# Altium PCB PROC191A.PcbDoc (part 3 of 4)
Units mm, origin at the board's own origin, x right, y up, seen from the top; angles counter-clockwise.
Board outline 150 x 100 mm, 6 copper layers (L1, L2, L3, L4, L5, L6), stack 1.608 mm thick; 309 components, 191 nets, 851 pads, 778 vias.
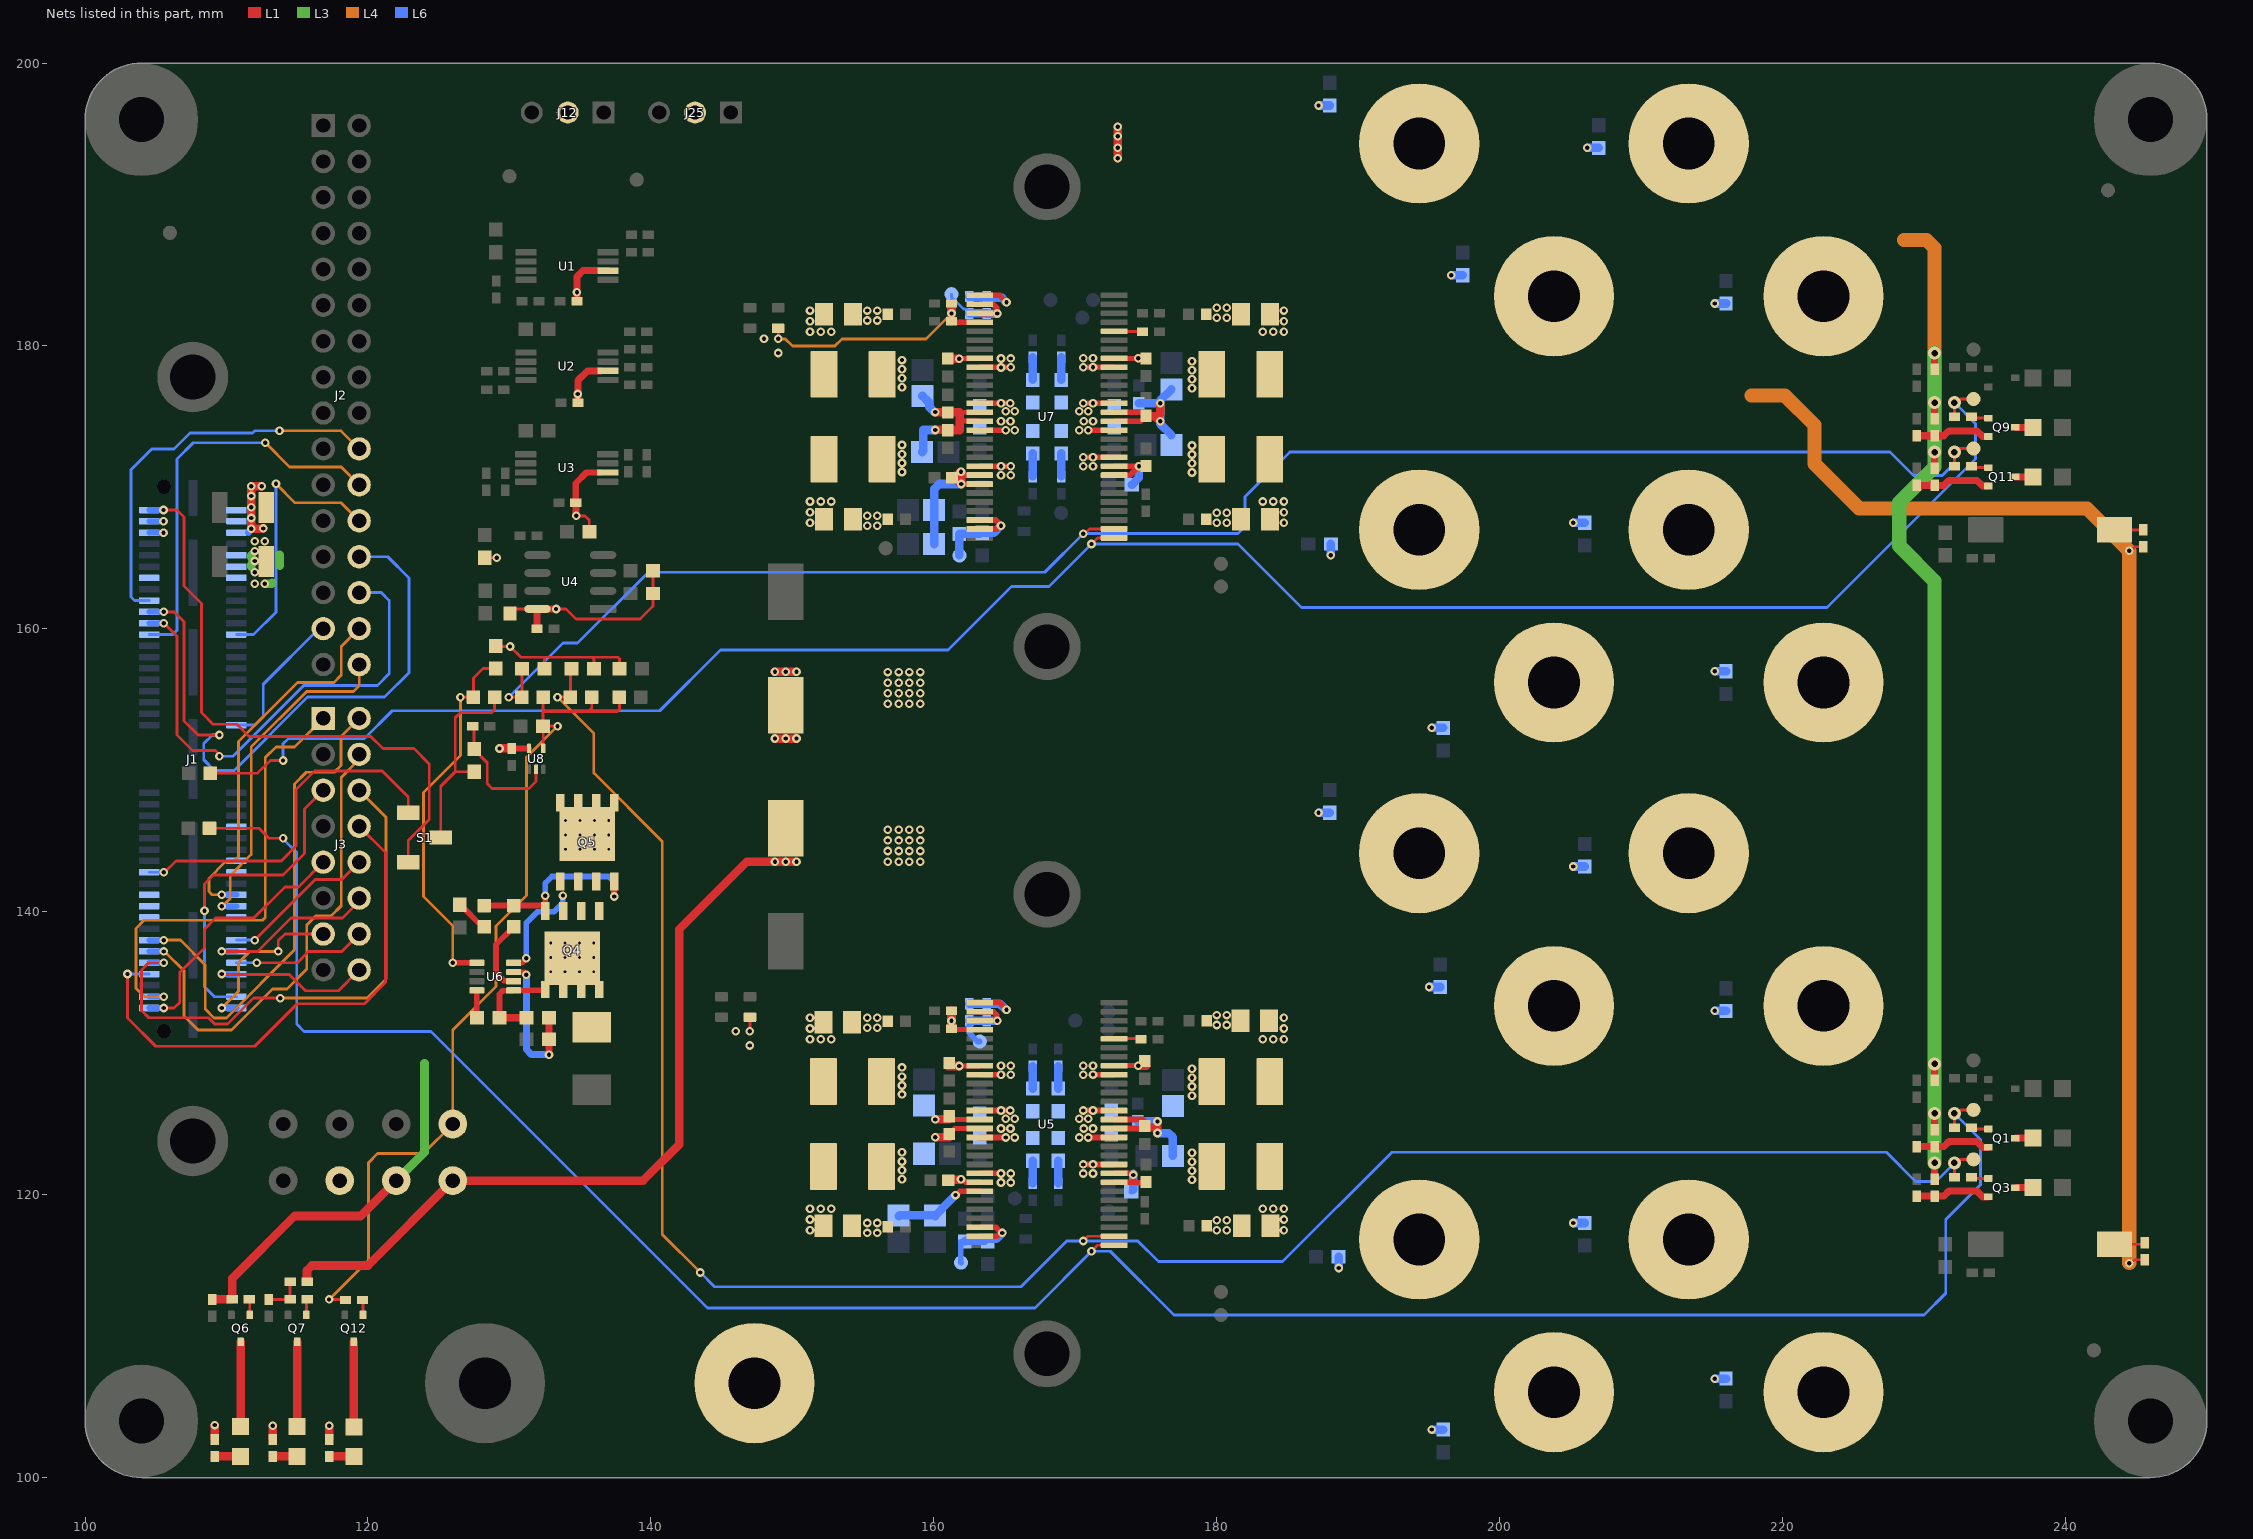
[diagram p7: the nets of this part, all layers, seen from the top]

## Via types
v1: diameter 0.61, hole 0.305, L1 to L6, tented both sides, 566 vias
v2: diameter 0.914, hole 0.457, L1 to L6, tented both sides, 188 vias
v3: diameter 0.5, hole 0.2, L1 to L6, 24 vias

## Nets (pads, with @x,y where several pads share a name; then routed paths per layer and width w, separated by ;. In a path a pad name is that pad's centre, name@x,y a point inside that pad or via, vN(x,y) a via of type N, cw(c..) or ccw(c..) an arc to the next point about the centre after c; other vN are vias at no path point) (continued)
MCASPX_SERIAL7: J1.40 J2.29 | length 10.3
  L6 w0.2: J1.40@110.705,153.2 111.998,153.2 112.6,153.802 112.6,156.08 116.54,160.02 J2.29@116.84,160.02
McASPy_ACLKR: J1.78 J3.5 | length 22.8
  L1 w0.2: v1(108.445,140.068) 108.445,141.958 109.092,142.605 113.986,142.605 115.506,144.125 115.506,147.256 J3.5@116.84,148.59
  L6 w0.2: v1(108.445,140.068) 108.445,134.7 109.145,134 J1.78@110.705,134
McASPy_ACLKX: J1.77 J3.1 | length 33.5
  L4 w0.2: v1(105.575,134) 104.2,134 103.605,134.595 103.605,138.83 104.18,139.405 112.555,139.405 112.735,139.584 112.735,150.885 113.495,151.645 114.815,151.645 J3.1@116.84,153.67
  L6 w0.4: J1.77@104.535,134 v1(105.575,134)
MCASPY_AFSR: J1.80 J3.13 | length 12
  L1 w0.2: v1(113.66,137.2) 113.66,137.96 114.13,138.43 J3.13@116.84,138.43
  L4 w0.2: v1(109.665,133.2) 110.85,134.385 110.85,136.4 111.65,137.2 v1(113.66,137.2)
  L6 w0.4: v1(109.665,133.2) J1.80@110.705,133.2
McASPy_AFSX: J1.79 J3.9 | length 18.6
  L1 w0.2: v1(105.575,133.2) 106.3,133.2 106.7,133.6 106.7,135.7 108.445,137.445 108.445,138.768 109.232,139.555 111.93,139.555 114.125,141.75 115.08,141.75 J3.9@116.84,143.51
  L6 w0.4: J1.79@104.535,133.2 v1(105.575,133.2)
McASPy_Serial0: J1.67 J3.2 | length 35.8
  L4 w0.2: v1(105.575,138) 106.75,138 108.5,136.25 108.5,133.117 109.117,132.5 110,132.5 114.815,137.315 114.815,149.038 115.637,149.86 117.615,149.86 118.1,150.345 118.1,152.39 J3.2@119.38,153.67
  L6 w0.4: J1.67@104.535,138 v1(105.575,138)
McASPy_Serial1: J1.69 J3.4 | length 34.4
  L4 w0.2: v1(105.575,137.2) 105.63,137.2 107,135.83 107,132.643 108,131.643 110.355,131.643 112.446,133.734 113.266,134.554 114.271,134.554 115.677,135.96 115.677,139.065 116.312,139.7 117.377,139.7 118.11,140.433 118.11,149.486 119.38,150.756 J3.4@119.38,151.13
  L6 w0.4: J1.69@104.535,137.2 v1(105.575,137.2)
McASPy_Serial2: J1.71 J3.6 | length 38.8
  L1 w0.2: v1(105.575,136.4) 104.51,136.4 104,135.89 104,133.022 104.51,132.512 108.738,132.512 109.17,132.08 110.08,132.08 111.9,133.9 v1(113.8,133.9)
  L4 w0.2: v1(113.8,133.9) 119.93,133.9 121.285,135.255 121.285,146.685 J3.6@119.38,148.59
  L6 w0.4: J1.71@104.535,136.4 v1(105.575,136.4)
McASPy_Serial3: J1.73 J3.8 | length 37.4
  L1 w0.2: v1(103,135.6) 103,132.5 105,130.5 112,130.5 115,133.5 119.75,133.5 121.25,135 121.25,144.18 J3.8@119.38,146.05
  L6 w0.2: v1(103,135.6) J1.73@104.535,135.6
McASPy_Serial4: J1.68 J3.10 | length 11
  L1 w0.2: v1(111.998,138) v1(111.998,138) 116.275,142.275 118.145,142.275 J3.10@119.38,143.51
  L6 w0.2: J1.68@110.705,138 v1(111.998,138)
McASPy_Serial5: J1.70 J3.12 | length 12.5
  L1 w0.2: v1(109.665,137.2) 112.2,137.2 114.555,139.555 118.205,139.555 119.38,140.73 J3.12@119.38,140.97
  L6 w0.4: v1(109.665,137.2) J1.70@110.705,137.2
McASPy_Serial6: J1.72 J3.14 | length 9.5
  L1 w0.2: v1(112.15,136.393) 115.003,136.393 115.81,137.2 118.15,137.2 J3.14@119.38,138.43
  L6 w0.2: J1.72@110.705,136.4 110.708,136.397 112.146,136.397 v1(112.15,136.393)
McASPy_Serial7: J1.74 J3.16 | length 11.9
  L1 w0.2: v1(109.665,135.6) 109.705,135.56 114.44,135.56 115.582,134.418 117.908,134.418 J3.16@119.38,135.89
  L6 w0.4: v1(109.665,135.6) J1.74@110.705,135.6
NetC15_2: C15.2 R26.1 | length 1.6
  L6 w0.6: C15.2@168.8,120.8 R26.1@168.8,122.4
NetC25_2: C25.2 R31.1 | length 1.6
  L6 w0.6: R31.1@168.8,127.5 C25.2@168.8,129.1
NetC28_1: C28.1 R96.2 U8.2 | length 9.1
  L1 w0.2: C28.1@127.4,153.134 127.5,153.034 127.5,151.475 128.438,150.537 128.438,149.062 128.775,148.725 131.392,148.725 131.886,149.219 U8.2@131.886,150.065
NetC46_2: C46.2 R34.1 | length 1.6
  L6 w0.6: C46.2@167,120.8 R34.1@167,122.4
NetC56_2: C56.2 R36.1 | length 1.6
  L6 w0.6: R36.1@167,127.5 C56.2@167,129.1
NetC64_1: C64.1 R55.1 | length 2.4
  L1 w0.4: C64.1@126.5,140.5 126.5,140.475 126.775,140.2 126.841,140.2 127.821,139.22 127.952,139.22 R55.1@128.23,138.941
NetC73_2: C73.2 R71.1 | length 1.6
  L6 w0.6: C73.2@169,170.8 R71.1@169,172.4
NetC83_2: C83.2 R76.1 | length 1.6
  L6 w0.6: R76.1@169,177.6 C83.2@169,179.2
NetC104_2: C104.2 R79.1 | length 1.6
  L6 w0.6: C104.2@167,170.8 R79.1@167,172.4
NetC114_2: C114.2 R81.1 | length 1.6
  L6 w0.6: R81.1@167,177.6 C114.2@167,179.2
NetD5_1: D5.1 R56.1 | length 1.7
  L1 w0.6: R56.1@109.167,101.4 R56.1@109.167,101.419 ; R56.1@109.35,101.519 109.635,101.519 D5.1@111,101.5
NetD5_2: D5.2 Q6.3 | length 6
  L1 w0.6: D5.2@111,103.6 Q6.3@111,109.6
NetD6_1: D6.1 R57.1 | length 1.7
  L1 w0.6: R57.1@113.278,101.5 D6.1@115,101.5
NetD6_2: D6.2 Q7.3 | length 6.3
  L1 w0.6: D6.2@115,103.35 D6.2@115,103.6 Q7.3@115,109.6
NetD11_1: D11.1 R5.1 | length 1.8
  L1 w0.6: R5.1@117.253,101.5 119,101.5 D11.1@119.01,101.49
NetD11_2: D11.2 Q12.3 | length 6
  L1 w0.6: D11.2@119,103.6 Q12.3@119,109.6
NetQ6_1: Q6.1 R61.2 | length 1.3
  L1 w0.2: Q6.1@111.65,111.5 R61.2@111.65,112.75
NetQ7_1: Q7.1 R62.2 | length 1.3
  L1 w0.2: Q7.1@115.65,111.5 R62.2@115.65,112.75
NetQ12_1: Q12.1 R27.2 | length 1.1
  L1 w0.2: R27.2@119.61,112.559 119.65,112.519 Q12.1@119.65,111.5
NetR47_1: R47.1 SW2.1 | length 2
  L1 w0.2: SW2.1@243.464,116.5 R47.1@245.5,116.5
NetR59_2: R59.2 R62.1 R65.1 | length 2.5
  L1 w0.2: R65.1@113,112.6 R62.1@114.275,112.6 ; R62.1@114.5,112.6 R59.2@114.5,113.85
NetR90_1: R90.1 SW4.1 | length 2
  L1 w0.2: SW4.1@243.464,167 R90.1@245.5,167
OUT_1M_J0: C108.2 C111.1 C113.1 J24.1 U7.37 | length 2.6
  L1 w0.4: U7.37@163.25,178.493 165.075,178.493
  L6 w0.61: v1(206.2,194) C113.1@207,194
  other v1: 164.75,178.48 165.431,178.483 164.75,179.115 165.431,179.118 155.3,181.8 156,181.8 155.3,182.5 156,182.5
OUT_1M_J1: C50.2 C53.1 C55.1 J11.1 U5.37 | length 2
  L1 w0.4: U5.37@163.25,128.493 164.415,128.493
  L6 w0.61: v1(205.2,143.2) C55.1@206,143.2
  other v1: 164.75,128.48 165.431,128.483 164.75,129.115 165.431,129.118 155.3,131.8 156,131.8 155.3,132.5 156,132.5
OUT_1P0: C80.2 L9.1 R81.2 U7.41 | length 1.8
  L1 w0.4: U7.41@163.25,175.953 165.075,175.953
  other v1: 165.075,175.378 165.725,175.378 164.75,175.953 165.4,175.953 157.75,177.091 157.75,177.722 157.75,178.353 157.75,179
OUT_1P1: C22.2 L4.1 R36.2 U5.41 | length 1.8
  L1 w0.4: U5.41@163.25,125.953 165.075,125.953
  other v1: 165.075,125.378 165.725,125.378 164.75,125.953 165.4,125.953 157.75,127.091 157.75,127.722 157.75,128.353 157.75,129
OUT_1P_J0: C108.1 C112.1 J23.1 L9.2 | length 0.8
  L6 w0.61: v1(187.2,197) C112.1@188,197
  other v1: 151.25,181 152,181 152.75,181 151.25,181.75 151.25,182.5
OUT_1P_J1: C50.1 C54.1 J10.1 L4.2 | length 0.8
  L6 w0.61: v1(187.2,147) C54.1@188,147
  other v1: 151.25,131 152,131 152.75,131 151.25,131.75 151.25,132.5
OUT_2M_J0: C91.2 C93.1 C95.1 J22.1 U7.48 | length 2.6
  L1 w0.4: U7.48@163.25,171.508 165.075,171.508
  L6 w0.61: v1(215.2,157) C95.1@216,157
  other v1: 155.3,167.3 156,167.3 155.3,168 156,168 164.75,170.863 165.431,170.865 164.75,171.498 165.431,171.5
OUT_2M_J1: C33.2 C35.1 C37.1 J9.1 U5.48 | length 2
  L1 w0.4: U5.48@163.25,121.508 164.415,121.508
  L6 w0.61: v1(215.2,107) C37.1@216,107
  other v1: 155.3,117.3 156,117.3 155.3,118 156,118 164.75,120.863 165.431,120.865 164.75,121.498 165.431,121.5
OUT_2P0: C75.2 L8.1 R79.2 U7.44 | length 1.8
  L1 w0.4: U7.44@163.25,174.048 v1(165.075,174.048)
  other v1: 157.75,171.091 157.75,171.722 157.75,172.353 157.75,173 165.725,174.048 164.75,174.679 165.425,174.679
OUT_2P1: C17.2 L3.1 R34.2 U5.44 | length 1.8
  L1 w0.4: U5.44@163.25,124.048 v1(165.075,124.048)
  other v1: 157.75,121.091 157.75,121.722 157.75,122.353 157.75,123 165.725,124.048 164.75,124.679 165.425,124.679
OUT_2P_J0: C91.1 C94.1 J21.1 L8.2 | length 0.8
  L6 w0.61: v1(195.2,153) C94.1@196,153
  other v1: 151.25,167.5 151.25,168.25 151.25,169 152,169 152.75,169
OUT_2P_J1: C33.1 C36.1 J8.1 L3.2 | length 0.8
  L6 w0.61: v1(195.2,103.4) C36.1@196,103.4
  other v1: 151.25,117.5 151.25,118.25 151.25,119 152,119 152.75,119
OUT_3M_J0: C78.2 C79.1 C82.1 J20.1 U7.20 | length 2.6
  L1 w0.4: 170.925,178.493 U7.20@172.75,178.493
  L6 w0.61: v1(215.2,183) C82.1@216,183
  other v1: 170.569,178.49 171.25,178.493 170.569,179.125 171.25,179.128 180,182 180.7,182 180,182.7 180.7,182.7
OUT_3M_J1: C20.2 C21.1 C24.1 J7.1 U5.20 | length 2
  L1 w0.4: 171.585,128.493 U5.20@172.75,128.493
  L6 w0.61: v1(215.2,133) C24.1@216,133
  other v1: 170.569,128.49 171.25,128.493 170.569,129.125 171.25,129.128 180,132 180.7,132 180,132.7 180.7,132.7
OUT_3P0: C72.2 L7.1 R76.2 U7.16 | length 1.8
  L1 w0.4: 170.925,175.953 U7.16@172.75,175.953
  other v1: 170.275,175.378 170.925,175.378 170.575,175.953 171.25,175.953 178.25,177 178.25,177.647 178.25,178.278 178.25,178.909
OUT_3P1: C14.2 L2.1 R31.2 U5.16 | length 1.8
  L1 w0.4: 170.925,125.953 U5.16@172.75,125.953
  other v1: 170.275,125.378 170.925,125.378 170.575,125.953 171.25,125.953 178.25,127 178.25,127.647 178.25,128.278 178.25,128.909
OUT_3P_J0: C78.1 C81.1 J19.1 L7.2 | length 0.8
  L6 w0.61: v1(196.582,185) C81.1@197.383,185
  other v1: 183.25,181 184,181 184.75,181 184.75,181.75 184.75,182.5
OUT_3P_J1: C20.1 C23.1 J6.1 L2.2 | length 0.8
  L6 w0.61: v1(195.01,134.686) C23.1@195.81,134.686
  other v1: 183.25,131 184,131 184.75,131 184.75,131.75 184.75,132.5
OUT_4M_J0: C66.2 C67.1 C69.1 J18.1 U7.10 | length 2.6
  L1 w0.4: 170.925,172.143 U7.10@172.75,172.143
  L6 w0.61: v1(205.2,167.5) C69.1@206,167.5
  other v1: 180,167.5 180.7,167.5 180,168.2 180.7,168.2 170.57,171.498 171.25,171.498 170.57,172.143 171.25,172.143
OUT_4M_J1: C8.2 C9.1 C11.1 J5.1 U5.10 | length 2.6
  L1 w0.4: 170.925,122.143 U5.10@172.75,122.143
  L6 w0.61: v1(205.2,118) C11.1@206,118
  other v1: 180,117.5 180.7,117.5 180,118.2 180.7,118.2 170.57,121.498 171.25,121.498 170.57,122.143 171.25,122.143
OUT_4P0: C65.2 L6.1 R71.2 U7.13 | length 1.8
  L1 w0.4: v1(170.925,174.048) U7.13@172.75,174.048
  other v1: 178.25,171.051 178.25,171.698 178.25,172.329 178.25,172.96 170.275,174.048 170.6,174.679 171.25,174.679
OUT_4P1: C7.2 L1.1 R26.2 U5.13 | length 1.8
  L1 w0.4: v1(170.925,124.048) U5.13@172.75,124.048
  other v1: 178.25,121.051 178.25,121.698 178.25,122.329 178.25,122.96 170.275,124.048 170.6,124.679 171.25,124.679
OUT_4P_J0: C66.1 C68.1 J17.1 L6.2 | length 0.8
  L6 w0.61: v1(188.068,165.2) C68.1@188.068,166
  other v1: 184.75,167.5 184.75,168.25 183.25,169 184,169 184.75,169
OUT_4P_J1: C8.1 C10.1 J4.1 L1.2 | length 0.8
  L6 w0.61: v1(188.617,114.817) C10.1@188.617,115.618
  other v1: 184.75,117.5 184.75,118.25 183.25,119 184,119 184.75,119
PD_LEDPWR0: Q11.2 R63.2 R72.1 | length 5.3
  L1 w0.5: R72.1@229.5,170.15 R63.2@230.75,170.15 231.405,170.15 ; 231.455,170.205 231.75,170.5 233.75,170.5 234.15,170.1 Q11.2@234.55,170.1
PD_LEDPWR1: Q3.2 R40.2 R45.1 | length 5.3
  L1 w0.5: R45.1@229.5,119.9 R40.2@230.75,119.9 231.405,119.9 ; 231.455,119.955 231.75,120.25 233.75,120.25 234.15,119.85 Q3.2@234.55,119.85
PD_N0: R93.2 R94.1 R95.1 TP32.1 U7.2 | length 119.8
  L1 w0.2: v1(129.963,155.177) R95.1@130.878,155.177 R94.1@130.878,157.177 ; v1(170.575,166.733) 170.686,166.733 171.016,167.063 U7.2@172.75,167.063 ; R93.2@232.15,171.5 v2(232.15,172.5) ; v2@232.343,172.5 232.593,172.75 TP32.1@233.5,172.75
  L6 w0.2: v1(129.963,155.177) 133.78,158.995 134.818,158.995 139.823,164 167.843,164 v1(170.575,166.733) 181.5,166.733 182,167.233 182,169.338 185.098,172.436 ; 185.162,172.5 227.596,172.5 229.246,170.85 231.291,170.85 232.15,171.709 v2(232.15,172.5)
PD_N1: R48.2 R54.1 R83.1 TP16.1 U5.2 | length 148.2
  L1 w0.2: v1(133.4,155.177) R83.1@134.316,155.177 134.316,157.114 R54.1@134.379,157.177 ; v1(170.575,116.733) 170.905,117.063 U5.2@172.75,117.063 ; R48.2@232.15,121.25 v2(232.15,122.25) 232.343,122.25 232.593,122.5 TP16.1@233.5,122.5
  L4 w0.2: v1(133.4,155.177) 135.968,152.61 135.968,149.81 140.806,144.972 140.806,117.194 v1(143.5,114.5)
  L6 w0.2: v1(143.5,114.5) 144.5,113.5 166.169,113.5 169.402,116.733 v1(170.575,116.733) 174.417,116.733 175.872,115.277 184.656,115.277 192.38,123 227.341,123 229.402,120.939 230.839,120.939 v2(232.15,122.25)
PD_N_L0: D10.1 Q11.3 | length 1.3
  L1 w0.5: Q11.3@236.45,170.75 D10.1@237.7,170.75
PD_N_L1: D3.1 Q3.3 | length 1.3
  L1 w0.5: Q3.3@236.45,120.5 D3.1@237.7,120.5
PD_N_R0: Q11.1 R93.1 | length 1.1
  L1 w0.2: R93.1@233.45,171.4 Q11.1@234.55,171.4
PD_N_R1: Q3.1 R48.1 | length 1.1
  L1 w0.2: R48.1@233.45,121.15 Q3.1@234.55,121.15
PLL_BYP0: C109.1 C110.1 TP28.1 U7.30 U7.31 | length 6.9
  L1 w0.4: U7.31@163.246,182.299 164.489,182.299 164.439,182.348 164.439,182.7 164.226,182.913 ; U7.30@163.25,182.938 164.201,182.938
  L6 w0.2: TP28.1@161.25,183.658 161.25,183.441 162.089,182.603 162.183,182.603 162.194,182.591 162.3,182.591 162.488,182.403 162.5,182.403 C110.1@162.5,182.303
  L6 w0.6: C110.1@162.5,182.303 C109.1@163.75,182.3 ; C109.1@163.75,182.292 v1(164.489,182.291)
PLL_BYP1: C51.1 C52.1 TP12.1 U5.30 U5.31 | length 6.8
  L1 w0.4: U5.31@163.246,132.299 v1(164.489,132.299) 164.439,132.348 164.439,132.7 164.226,132.913 ; U5.30@163.25,132.938 164.201,132.938
  L6 w0.4: C52.1@162.5,132.303 162.502,132.301 162.502,131.428 163.094,130.836 TP12.1@163.25,130.836 ; v1@164.487,132.301 v1(164.489,132.299)
  L6 w0.6: C52.1@162.502,132.301 v1@164.487,132.301
PORZ: R4.2 R27.1 R38.2 R83.2 R95.2 TP5.1 U8.4 | length 62.4
  L1 w0.2: v1(117.253,112.6) 118.369,112.6 R27.1@118.41,112.559 ; R95.2@132.38,155.177 132.38,154.156 ; U8.4@132.386,151.545 R38.2@132.386,153.127 ; v1(133.405,153.127) R38.2@132.386,153.127 ; R83.2@135.817,155.177 135.817,154.4 135.573,154.156 ; R4.2@137.776,155.177 137.776,154.284 137.648,154.156 135.573,154.156 ; 132.38,154.156 135.573,154.156 ; 132.38,154.156 132.38,153.134 R38.2@132.386,153.127
  L4 w0.2: v1(117.253,112.6) 117.26,112.6 120.03,115.37 120.03,122.256 120.678,122.905 123.905,122.905 TP5.1@126,125 126,131.664 129.053,134.717 129.053,139 131.2,141.147 131.2,150.922 v1(133.405,153.127)
PORZ_AEC: J1.1 S1.3 | length 42.2
  L1 w0.2: v1(105.55,168.4) 106.5,168.4 107,167.9 107,163.02 108.225,161.795 108.225,154.081 109.05,153.256 110.744,153.256 111.6,152.4 120.2,152.4 121.055,151.545 123.248,151.545 124.335,150.458 124.335,146.523 122.85,145.038 S1.3@122.85,143.5
  L6 w0.4: J1.1@104.535,168.4 v1(105.55,168.4)
PORZ_SELECT: R53.2 R96.1 S1.2 | length 14.1
  L1 w0.2: S1.2@125.15,145.25 125.15,148.875 126.175,149.9 ; R96.1@127.5,149.9 126.175,149.9 ; R53.2@128.955,155.177 128.955,154.286 128.753,154.084 126.538,154.084 126.175,153.722 126.175,149.9
PVDD: C26.1 C27.1 C29.1 C30.1 C32.1 C38.2 C39.2 C40.2 C41.2 C42.2 C43.2 C44.2 C45.2 C47.2 C48.1 C49.1 C59.1 C84.1 C85.1 C87.1 C88.1 C96.2 C97.2 C98.2 C99.2 C100.2 C101.2 C102.2 C103.2 C105.2 C106.1 C107.1 Q5.5 Q5.6 Q5.7 Q5.8 Q5.9 R59.1 TP6.1 U5.8 U5.9 U5.14 U5.15 U5.21 U5.36 U5.42 U5.43 U5.49 U5.50 U7.8 U7.9 U7.14 U7.15 U7.21 U7.36 U7.42 U7.43 U7.49 U7.50 | length 140.7
  L1 w0.3: C39.2@161.024,121.014 C39.2@161.067,121.057 ; v1@161.843,121.101 v1(161.927,121.101) ; v1@161.883,121.057 v1(161.927,121.101) ; v1@162.011,121.101 v1(161.927,121.101) ; U5.49@163.2,120.923 U5.49@163.25,120.873 ; U7.49@163.2,170.923 U7.49@163.25,170.873
  L1 w0.35: C40.2@161.024,125.324 161.034,125.314 U5.42@163.246,125.314 ; C97.2@161.024,175.324 U7.42@163.246,175.314 ; C38.2@161.1,124.3 161.1,124.322 161.331,124.553 161.353,124.553 161.479,124.679 U5.43@163.246,124.679 ; v1@162.004,170.234 U7.50@163.246,170.234 ; v1@162.004,170.869 U7.49@163.246,170.869 ; 162.004,174.679 U7.43@163.246,174.679 ; v1@162.045,129.103 163.225,129.103 U5.36@163.25,129.128 ; v1@162.045,179.103 163.225,179.103 U7.36@163.25,179.128 ; U5.21@172.75,129.128 v1(174.45,129.125) ; U7.21@172.75,179.128 v1(174.45,179.125)
  L1 w0.381: v1@161.983,171.101 162.212,170.873
  L1 w0.4: v1(161.534,119.977) 161.59,119.977 161.851,120.238 U5.50@163.25,120.238 ; C103.2@161.682,171.06 161.866,171.06 161.887,171.06 v1(161.927,171.101) v1@161.983,171.101 ; v1@161.927,170.241 161.939,170.241 v1@161.943,170.238 ; v1@161.927,170.241 v1@161.939,170.229 ; v1@162.091,121.051 162.269,120.873 U5.49@163.25,120.873 U5.49@163.281,120.873 ; U5.8@172.75,120.873 174.1,120.865 ; U5.9@172.75,121.508 174.1,121.5 174.1,120.865 ; U5.14@172.75,124.683 174.637,124.683 175,125.046 175,125.089 174.771,125.318 U5.15@172.75,125.318 ; U7.8@172.75,170.873 173.75,170.863 173.858,170.863 174.495,171.5 v1(174.5,171.5) ; U7.9@172.75,171.508 v1@174.21,171.508 ; U7.14@172.75,174.683 174.637,174.683 175,175.046 C102.2@175,175.067 175,175.089 174.771,175.318 U7.15@172.75,175.318 ; C45.2@174.9,120.849 174.116,120.849 174.1,120.865 ; C44.2@174.957,124.883 C44.2@175.021,124.947 ; C102.2@174.957,175.132 C102.2@175.021,175.196
  L1 w0.6: 142,138.753 146.793,143.547 v1(148.768,143.547) v1(149.53,143.547) v1(150.292,143.547) ; v1(148.768,152.247) v1(149.53,152.247) v1(150.292,152.247) ; v1(148.768,156.973) v1(149.53,156.973) v1(150.292,156.973) ; C39.2@161.067,121.057 v1@161.883,121.057 ; C44.2@175,124.818 175.049,124.769 175.812,124.769 ; C102.2@175,175.067 175.049,175.018 175.812,175.018 ; v1(175.812,124.363) 175.812,124.769 ; v1(175.812,125.176) 175.812,124.769 ; v1(175.997,174.679) 175.997,174.681 175.812,174.866 175.812,175.018 ; v1(176,175.953) 175.998,175.951 175.998,175.204 175.812,175.018
  L1 w0.61: R59.1@115.7,113.85 115.693,113.85 115.688,113.855 115.688,114.643 116.045,115 120,115 TP6.1@126,121 139.447,121 142,123.553 142,138.753 ; v1(160.1,124.062) C38.2@160.901,124.063 ; v1(160.1,125.324) C40.2@160.901,125.325 ; v1(160.1,174.062) C98.2@160.901,174.063 ; v1(160.1,175.324) C97.2@160.901,175.325 ; C41.2@161,129.1 161.1,129.1 v1(161.801,129.101) ; C96.2@161,179.1 v1(161.801,179.101) ; C38.2@161.024,124.062 C38.2@161.1,124.062 ; C40.2@161.024,125.324 C40.2@161.1,125.324 ; C98.2@161.024,174.062 161.825,174.062 161.825,175.324 C97.2@161.024,175.324 ; C103.2@161.3,170.7 C103.2@161.322,170.7 ; v1@161.927,170.241 v1@161.939,170.241 ; v1(174.45,129.125) C42.2@175,129.125 ; v1(174.45,179.125) C101.2@175,179.125 ; v1(174.5,171.5) C100.2@175,171.5 ; C103.2@161.322,170.7 161.933,170.233 161.939,170.229 v1(161.939,170.241) ; C103.2@161.322,170.7 161.866,171.06 v1(161.927,171.101) 161.932,170.709 v1(161.939,170.241)
  L6 w0.4: C47.2@173.961,120.209 C47.2@174.1,120.348 ; v1@175.715,125.2 175.8,125.115 v1@175.8,125.1
  L6 w0.6: C49.1@157.512,118.477 157.584,118.549 160.029,118.549 C48.1@160.101,118.477 ; C48.1@160.1,118.543 160.119,118.543 160.578,119.002 160.578,119.021 v1(161.534,119.977) ; C105.2@173.99,170.18 174.015,170.18 174.19,170.355 174.19,170.38 174.498,170.688 174.498,171.498 v1(174.5,171.5) ; C47.2@174.1,120.348 v1@174.1,121.5 ; C43.2@174.4,125.2 v1@175.715,125.2 ; C99.2@174.5,175.953 v1(176,175.953) ; v1(175.812,124.363) 175.814,124.361 176.601,124.361 176.9,124.062 C30.1@176.9,122.749 ; C88.1@176.8,173.7 176.799,173.7 175.999,174.499 175.999,174.677 v1(175.997,174.679) 175.996,174.681 175.996,175.072 175.998,175.075 175.998,175.951 v1(176,175.953) ; C87.1@176.8,176.932 C87.1@176.8,176.932 176.002,176.135 176.002,175.954 v1(176,175.953)
  L6 w0.61: C84.1@159.175,172.5 159.262,172.588 159.262,174.062 v1(160.1,174.062) ; C85.1@159.2,176.461 159.201,176.461 159.673,175.99 159.673,175.681 160.03,175.324 v1(160.1,175.324) ; C107.1@160.025,166 160.025,169.884 160.382,170.241 v1(161.939,170.241)
  other v1: 174.1,121.4 156.75,143.547 157.512,143.547 158.274,143.547 159.036,143.547 156.75,144.297 157.512,144.297 158.274,144.297 159.036,144.297 156.75,145.047 157.512,145.047 158.274,145.047 159.036,145.047 156.75,145.797 157.512,145.797 158.274,145.797 159.036,145.797 156.75,154.697 157.512,154.697 158.274,154.697 159.036,154.697 156.75,155.447 157.512,155.447 158.274,155.447 159.036,155.447 156.75,156.197 157.512,156.197 158.274,156.197 159.036,156.197 156.75,156.947 157.512,156.947 158.274,156.947 159.036,156.947
  other v3: 133.976,144.421 134.992,144.421 136.008,144.421 137.024,144.421 133.976,145.437 134.992,145.437 136.008,145.437 137.024,145.437 133.976,146.453 134.992,146.453 136.008,146.453 137.024,146.453
PVDD_CONN: C63.1 D4.2 J13.1 Q4.5 Q4.6 Q4.7 Q4.8 Q4.9 R50.2 U6.5 | length 7.3
  L1 w0.4: C63.1@129.3,132.512 129.3,134.184 129.534,134.418 130.275,134.418 U6.5@130.3,134.443 ; U6.5@130,134.443 U6.5@130.3,134.443 ; Q4.5@132.484,134.443 132.539,134.498 Q4.5@132.539,134.506 132.476,134.443 U6.5@130.3,134.443
  L1 w0.5: C63.1@129.3,132.512 R50.2@131.2,132.512
  other v3: 132.92,135.763 133.936,135.763 134.952,135.763 135.968,135.763 132.92,136.779 133.936,136.779 134.952,136.779 135.968,136.779 132.92,137.795 133.936,137.795 134.952,137.795 135.968,137.795
PWM1: J1.3 | length 1
  L6 w0.4: J1.3@104.535,167.6 v1(105.55,167.6)
PWM2: J1.5 | length 1
  L6 w0.4: J1.5@104.535,166.8 v1(105.55,166.8)
RESERVED1: J1.13
RESERVED3: J1.59
RESERVED4: J1.61
RESERVED5: J1.63
RESERVED6: J1.14
RESERVED7: J1.48
RESERVED8: J1.54
RESERVED9: J1.56
RESERVED10: J1.64
RESETSTATZ_AEC: J1.55 S1.1 | length 25.5
  L1 w0.2: v1(105.575,142.8) 105.63,142.8 106.43,143.6 113.874,143.6 114.925,144.651 114.925,148.64 116.232,149.947 121.014,149.947 122.85,148.111 S1.1@122.85,147
  L6 w0.2: J1.55@104.535,142.8 v1(105.575,142.8)
SDOUT_R0: R78.2 U7.24 | length 2
  L1 w0.2: U7.24@172.75,181.033 174.718,181.033 R78.2@174.75,181
SDOUT_R1: R33.2 U5.24 | length 2
  L1 w0.2: U5.24@172.75,131.033 174.718,131.033 R33.2@174.75,131
SPI_CLK: J1.17 J2.20 | length 28.2
  L4 w0.2: v1(113.75,174) 118.1,174 J2.20@119.38,172.72
  L6 w0.2: J1.17@104.535,162 103.5,162 103.25,162.25 103.25,171.25 104.72,172.72 106.286,172.72 107.41,173.845 111.845,173.845 112,174 v1(113.75,174)
SPI_CS0: J1.23 J2.22 | length 28.8
  L4 w0.2: v1(112.75,173.16) 114.46,171.45 118.11,171.45 J2.22@119.38,170.18
  L6 w0.2: J1.23@104.535,159.6 106.2,159.6 106.5,159.9 106.5,172.006 107.654,173.16 v1(112.75,173.16)
SPI_CS1: J1.24 J2.24 | length 19.5
  L4 w0.2: v1(113.5,170.256) 114.846,168.91 118.11,168.91 J2.24@119.38,167.64
  L6 w0.2: J1.24@110.705,159.6 111.921,159.6 113.5,161.179 v1(113.5,170.256)
SPI_D0: J1.19 J2.26 | length 43.7
  L1 w0.2: v1(105.575,161.2) 106.304,161.2 107,160.504 107,153.5 108,152.5 v1(109.5,152.5)
  L6 w0.2: v1(109.5,152.5) 109,152.5 108.395,151.895 108.395,150.749 109.145,150 110.55,150 115.727,155.177 121.177,155.177 122.9,156.9 122.9,163.6 121.4,165.1 J2.26@119.38,165.1
  L6 w0.4: J1.19@104.535,161.2 v1(105.575,161.2)
SPI_D1: J1.21 J2.28 | length 35
  L1 w0.2: v1(105.575,160.4) 106.5,159.475 106.5,152.5 107.595,151.405 109.215,151.405 109.332,151.288 109.332,151.279 109.5,151.111 v1(109.5,151)
  L6 w0.2: v1(109.5,151) 110.459,151 115.459,156 120.675,156 121.5,156.825 121.5,162 120.94,162.56 J2.28@119.38,162.56
  L6 w0.4: J1.21@104.535,160.4 v1(105.575,160.4)
STBY_LEDPWR0: Q9.2 R58.2 R60.1 | length 5.3
  L1 w0.5: R60.1@229.5,173.65 R58.2@230.75,173.65 231.405,173.65 ; 231.455,173.705 231.75,174 233.75,174 234.15,173.6 Q9.2@234.55,173.6
STBY_LEDPWR1: Q1.2 R37.2 R39.1 | length 5.3
  L1 w0.5: R39.1@229.5,123.4 R37.2@230.75,123.4 231.405,123.4 ; 231.455,123.455 231.75,123.75 233.75,123.75 234.15,123.35 Q1.2@234.55,123.35
STBY_N0: R86.1 R88.2 TP29.1 U7.1 | length 147.1
  L1 w0.2: R86.1@108.851,149.8 112.205,149.8 113.105,150.7 113.998,150.7 v1(114,150.698) ; v1(171.15,166) 171.577,166.428 U7.1@172.75,166.428 ; R88.2@232.15,175 v2(232.15,176) ; v2@232.343,176 232.593,176.25 TP29.1@233.5,176.25
  L6 w0.2: v1(114,150.698) 114,151.883 114.372,152.255 119.76,152.255 121.721,154.216 140.629,154.216 144.912,158.5 161,158.5 165.5,163 168.15,163 v1(171.15,166) 181.5,166 186,161.5 223.142,161.5 233.648,172.005 233.648,174.502 v2(232.15,176)
STBY_N1: R41.1 R43.2 TP13.1 U5.1 | length 166.6
  L1 w0.2: R41.1@108.8,145.9 108.805,145.905 112.295,145.905 113,145.2 v1(114,145.2) ; v1(171.15,116) 171.577,116.428 U5.1@172.75,116.428 ; R43.2@232.15,124.75 v2(232.15,125.75) ; v2@232.343,125.75 232.593,126 TP13.1@233.5,126
  L6 w0.2: v1(114,145.2) 114,145.154 114.969,144.186 114.969,132.071 115.489,131.55 124.45,131.55 144,112 167.15,112 v1(171.15,116) 172.477,116 176.977,111.5 230,111.5 231.537,113.037 231.537,118.245 234,120.707 234,123.9 v2(232.15,125.75)
STBY_N_L0: D8.1 Q9.3 | length 1.3
  L1 w0.5: Q9.3@236.45,174.25 D8.1@237.7,174.25
STBY_N_L1: D1.1 Q1.3 | length 1.3
  L1 w0.5: Q1.3@236.45,124 D1.1@237.7,124
STBY_N_R0: Q9.1 R88.1 | length 1.1
  L1 w0.2: R88.1@233.45,174.9 Q9.1@234.55,174.9
STBY_N_R1: Q1.1 R43.1 | length 1.1
  L1 w0.2: R43.1@233.45,124.65 Q1.1@234.55,124.65
UART_RX: J1.62 J2.32 | length 24.1
  L4 w0.2: v1(109.665,140.4) 109.72,140.4 110.27,140.949 110.27,142.57 111.745,144.045 111.745,151.645 115.675,155.575 118.975,155.575 119.38,155.98 J2.32@119.38,157.48
  L6 w0.4: v1(109.665,140.4) J1.62@110.705,140.4
UART_TX: J1.60 J2.30 | length 26.9
  L4 w0.2: v1@109.72,141.2 v1(109.665,141.2) 108.994,141.2 108.754,141.44 108.754,142.365 109.9,143.51 110.45,143.51 110.85,143.91 110.85,152.04 115.02,156.21 117.59,156.21 118.11,156.73 118.11,158.75 J2.30@119.38,160.02
  L6 w0.4: v1(109.665,141.2) J1.60@110.705,141.2
VDDIO: C2.2 C3.2 C4.2 C5.2 C6.2 C12.1 C13.1 C57.2 C70.1 C71.1 J1.10 J1.12 R2.1 R7.2 R8.2 R17.1 R18.1 R20.1 R28.2 R47.2 R52.2 R54.2 R61.1 R64.1 R73.2 R90.2 R94.2 TP33.1 U1.6 U2.6 U3.6 U4.8 U5.32 U7.32 U8.5 | length 179.5
  L1 w0.2: R8.2@128.27,165.024 v1(129.099,165.024) ; R52.2@129.032,158.788 129.07,158.75 v1(130.048,158.75) 130.798,158 132.435,158 ; R17.1@130.346,161.409 U4.8@131.911,161.409 ; R94.2@132.478,157.177 132.478,157.957 132.435,158 ; v1(133.3,161.409) 134,161.409 134.71,160.698 139.244,160.698 140.15,161.605 R18.1@140.15,162.5 R20.1@140.15,164.1 ; v1@134.745,167.979 135.347,167.979 135.64,167.686 R7.2@135.64,166.912 ; R54.2@135.979,157.177 135.979,157.838 135.817,158 ; R2.1@137.688,157.089 R2.1@137.776,157.177 137.776,157.883 137.659,158 135.817,158 ; v1(147,131.55) R28.2@147,132.55 ; v1(149,180.5) R73.2@149,181.25 ; v1(244.5,115.167) 244.928,115.406 R47.2@245.606,115.406 ; v1(244.5,165.514) 244.611,165.514 244.897,165.8 R90.2@245.5,165.8 ; 132.435,158 135.817,158
  L1 w0.35: R17.1@130.041,161.079 130.041,161.104 R17.1@130.346,161.409 ; U4.8@131.95,161.37 U4.8@131.949,161.371 ; U1.6@136.962,185.333 U1.6@136.972,185.322 ; C13.1@161.25,131.75 C13.1@161.308,131.693 ; C13.1@161.332,131.668 U5.32@163.25,131.668 ; U5.32@163.225,131.693 U5.32@163.25,131.668 ; U7.32@163.25,181.668 U7.32@163.257,181.675 ; U5.32@163.257,131.675 U5.32@163.25,131.668 ; U4.8@131.949,161.371 131.911,161.409 U4.8@131.986,161.409 U4.8@131.949,161.371
  L1 w0.4: C57.2@130.15,151.545 U8.5@131.386,151.545 ; C71.1@161.425,181.668 U7.32@163.25,181.668
  L1 w0.45: C5.2@134.7,168.9 134.7,170.3 135.45,171.05 U3.6@136.45,171.05
  L1 w0.5: C6.2@131.95,160 U4.8@131.95,161.37 ; U4.8@131.986,161.409 v1(133.3,161.409) ; C5.2@134.7,168.9 134.712,168.888 134.712,168.012 v1(134.724,168) v1@134.745,167.979 ; C3.2@134.773,183.148 v1(134.773,183.8) 134.773,184.895 135.2,185.322 U1.6@136.972,185.322 ; C4.2@134.85,176 134.844,176.006 134.844,176.595 v1(134.837,176.601) 134.858,176.622 134.858,177.57 135.524,178.236 U2.6@136.467,178.236 ; R7.2@135.64,166.912 R7.2@135.674,166.878
  L1 w0.6: R64.1@109,112.6 R61.1@110.4,112.6 ; v1(129.3,151.545) C57.2@130.15,151.545
  L1 w0.61: R61.1@110.4,112.6 110.4,114.084 114.816,118.5 119.5,118.5 TP33.1@122,121 TP33.1@122.118,121.118 ; v1@161.24,182.31 161.24,182.3 C71.1@161.25,181.75 ; C13.1@161.25,131.75 v1(161.25,132.3) C12.1@161.25,133 ; v1(161.25,182.3) C70.1@161.25,183
  L3 w0.6: 111.745,164.4 111.745,164.542 112,164.797 v1(112,164.8) 112,164.803 111.745,165.058 111.745,165.2 ; v1(112.7,163.2) 112.702,163.202 113.202,163.202 113.25,163.25 ; 113.75,164.45 113.75,165.25
  L3 w0.61: TP33.1@122,121 124,123 ; 124,123.168 124,123 ; 124,129.28 124,123
  L4 w0.2: v1(149,180.5) 149.5,180.5 150,180 153,180 153.5,180.5 159.45,180.5 v1(161.25,182.3)
  L4 w1: 217.81,176.5 220.155,176.5 222.25,174.405 222.25,171.668 225.418,168.5 241.514,168.5 v1(244.5,165.514) v1(244.5,115.167)
  other v1: 147,130.55 146,131.55 112,163.2 112,164 112,165.5 112,166.2 112.7,166.2 149,179.5 148,180.5
VIN1_EN: R52.1 R53.1 U6.1 | length 26.5
  L1 w0.2: v1(126.538,155.177) R53.1@127.453,155.177 127.453,156.522 128.132,157.2 129.02,157.2 R52.1@129.032,157.188
  L1 w0.4: v1(126,136.394) U6.1@127.7,136.393
  L4 w0.2: v1(126,136.394) 126,139 123.925,141.075 123.925,148.425 126.538,151.038 v1(126.538,155.177)
VIN1_GATE: Q4.4 Q5.4 R49.1 R55.2 | length 13.6
  L1 w0.4: R55.2@128.23,140.443 R49.1@130.316,140.443 132.434,140.443 Q4.4@132.539,140.338 ; v1(132.525,141.135) 132.539,141.121 Q4.4@132.539,140.338 ; Q4.4@132.539,140.068 Q4.4@132.539,140.338 ; v1@137.405,141.094 Q5.4@137.405,142.147
  L6 w0.4: v1(132.525,141.135) 132.54,141.149 132.54,142.04 133,142.5 137,142.5 137.418,142.082 v1(137.418,141.081)
VIN1_GATE_R: R49.2 U6.6 | length 5.3
  L1 w0.4: U6.6@130.3,135.093 130.275,135.118 129.638,135.118 129.053,135.703 129.053,137.682 130.313,138.941 R49.2@130.316,138.941
VIN1_OV: R50.1 R51.2 U6.7 | length 10.6
  L1 w0.4: U6.7@130.325,135.718 131.042,135.718 v1(131.2,135.56)
  L1 w0.5: v1(132.8,129.9) 132.802,129.902 132.802,130.986 R51.2@132.804,130.988 ; R50.1@132.8,132.512 132.802,132.51 R51.2@132.802,131.024
  L6 w0.5: v1(131.2,135.56) 131.2,130.263 131.563,129.9 v1(132.8,129.9)
VIN1_SRC: Q4.1 Q4.2 Q4.3 Q5.1 Q5.2 Q5.3 U6.8 | length 7.2
  L1 w0.4: U6.8@130.3,136.393 130.878,136.393 v1(131.2,136.715)
  L6 w0.4: v1(131.2,136.715) 131.2,139.224 131.976,140 133.14,140 133.782,140.642 v1(133.782,141.148)
VIN1_VCAP: C63.2 U6.4 | length 1.9
  L1 w0.4: C63.2@127.7,132.512 U6.4@127.7,134.443
VR_RET0: C109.2 C110.2 U7.29 | length 5
  L1 w0.4: U7.29@163.25,183.573 164.653,183.573 v1@165.139,183.086
  L6 w0.6: C110.2@162.5,183.491 C109.2@163.75,183.491 C109.2@163.75,183.399 ; C109.2@163.75,183.391 164.824,183.391 165.136,183.078 v1(165.139,183.078)
VR_RET1: C51.2 C52.2 U5.29 | length 4.9
  L1 w0.4: U5.29@163.25,133.573 164.653,133.573 v1(165.139,133.086)
  L6 w0.6: C52.2@162.5,133.503 C51.2@163.734,133.503 164.666,133.503 165.082,133.086 v1(165.139,133.086)
VREG0: C74.2 C76.1 TP23.1 U7.54 U7.55 | length 8
  L1 w0.4: U7.55@163.25,167.063 164.454,167.063 164.692,167.3 v1(164.748,167.3) 164.748,167.329 164.38,167.698 U7.54@163.25,167.698
  L6 w0.6: TP23.1@161.81,165.192 161.806,165.197 161.806,166.696 C76.1@161.801,166.7 161.817,166.716 163.234,166.716 C74.2@163.25,166.733 ; C74.2@163.25,166.758 163.285,166.792 164.238,166.792 164.746,167.3 v1(164.748,167.3)
VREG1: C16.2 C18.1 TP7.1 U5.54 U5.55 | length 7.8
  L1 w0.4: U5.55@163.25,117.063 164.454,117.063 164.692,117.3 v1@164.748,117.3 ; U5.54@163.25,117.698 164.39,117.698 164.395,117.693 164.399,117.693 164.792,117.3 v1(164.848,117.3) v1@164.848,117.323
  L6 w0.4: C18.1@161.902,116.674 161.902,115.226 TP7.1@161.929,115.2
  L6 w0.6: C18.1@162.2,116.7 162.26,116.76 163.618,116.76 163.734,116.877 164.425,116.877 v1(164.848,117.3)
VSYS5V0: C1.2 J1.2 J1.4 J1.6 J12.2 J25.2 R5.2 R37.1 R40.1 R42.1 R56.2 R57.2 R58.1 R63.1 R66.1 TP4.1 | length 93
  L1 w0.5: R40.1@230.75,121.1 v2(230.75,122.25) ; R37.1@230.75,124.6 v2(230.75,125.75) ; R42.1@230.75,128.1 v2(230.75,129.25) ; R63.1@230.75,171.35 v2(230.75,172.5) ; R58.1@230.75,174.85 v2(230.75,176) ; R66.1@230.75,178.35 v2(230.75,179.5)
  L1 w0.6: R56.2@109.167,102.7 v1(109.167,103.716) ; R57.2@113.278,102.7 v1(113.278,103.671) ; R5.2@117.253,102.7 117.253,103.672 117.257,103.675 v1(117.257,103.678)
  L1 w0.61: v1(112.5,170.072) v1(111.745,170.072) v1(111.745,169.392) v1(111.745,168.592) v1(111.745,167.837) v1(111.745,167.072) 112.572,167.072 v1(112.6,167.1) ; v1(173,193.265) v1(173,194.02) v1(173,194.82) v1(173,195.5)
  L3 w1: v2(230.75,122.25) v2(230.75,125.75) v2(230.75,129.25) 230.75,163.372 228.25,165.872 228.25,168.945 230.75,171.445 v2(230.75,172.5) v2(230.75,176) v2(230.75,179.5)
  L4 w1: 228.58,187.5 230.164,187.5 230.75,186.914 v2(230.75,179.5) v2(230.75,176) v2(230.75,172.5)
  L6 w0.5: 111.553,166.82 v1@111.639,166.906
pads on no net: FID1.1 FID2.1 FID3.1 FID4.1 FID5.1 FID6.1 J1. U1.5 U1.7 U3.5 U3.7 U4.1 U5.22 U5.51 U6.3 U7.22 U7.51 U8.1

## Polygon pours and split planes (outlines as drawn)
PVDD on L1 "L1_PVDD_P182" (solid, remove dead copper, pour order 182): 132.973,148.561 133.012,148.6 138,148.6 138,143.6 132.9,143.6 132.9,148.6
PVDD on L1 "L1_PVDD_P015" (solid, remove dead copper, pour order 15): 161.1,123.761 162.145,123.761 162.145,125.9 161.1,125.9
PVDD on L1 "L1_PVDD_P180" (solid, remove dead copper, pour order 180): 162.054,170.876 162.054,170.238 164.193,170.238 164.193,170.876
VSYS5V0 on L1 "L1_VSYS5V0_P020" (solid, remove dead copper, pour order 20): 111.164,167 114.164,167 ccw(c114.164,167.4) 114.564,167.4 116.364,167.4 116.364,176 116.364,182 121.364,187 172.752,187 173.748,187.666 173.748,195.616 172.864,196.5 111.864,196.5 110.864,195.5 110.864,167.3 ccw(c111.164,167.3)
GND on L1 "L1_GND_P149" (solid, remove dead copper, pour order 179): 104,200 246,200 cw(c246,196) 250,196 250,104 cw(c246,104) 246,100 104,100 cw(c104,104) 100,104 100,196 cw(c104,196)
VDDIO on L1 "L1_VDDIO_P016" (solid, remove dead copper, pour order 16): 111.4,162.8 113,162.8 113,166.5 111.4,166.5
PVDD on L1 "L1_PVDD_P178" (solid, remove dead copper, pour order 178): 162.054,175.321 162.054,174.683 164.193,174.683 164.193,175.321
PLL_BYP0 on L1 "L1_PLL_BYP0_P176" (solid, remove dead copper, pour order 176): 162.304,182.941 162.304,182.303 164.443,182.303 164.443,182.941
PVDD on L1 "L1_PVDD_P166" (solid, remove dead copper, pour order 166): 171.804,175.321 171.804,174.683 174.818,174.683 174.818,175.321
PVDD on L1 "L1_PVDD_P165" (solid, remove dead copper, pour order 165): 171.804,171.511 171.804,170.873 174.1,170.873 174.1,171.511
VREG0 on L1 "L1_VREG0_P164" (solid, remove dead copper, pour order 164): 162.304,167.701 162.304,167.063 164.564,167.063 164.564,167.701
VREG1 on L1 "L1_VREG1_P163" (solid, remove dead copper, pour order 163): 162.304,117.701 162.304,117.063 164.595,117.063 164.595,117.701
PVDD on L1 "L1_PVDD_P162" (solid, remove dead copper, pour order 162): 171.804,125.321 171.804,124.683 174.818,124.683 174.818,125.321
PVDD on L1 "L1_PVDD_P161" (solid, remove dead copper, pour order 161): 171.804,121.511 171.804,120.873 173.943,120.873 173.943,121.511
PVDD on L1 "L1_PVDD_P160" (solid, remove dead copper, pour order 160): 162.054,125.318 162.054,124.679 164.193,124.679 164.193,125.318
PLL_BYP1 on L1 "L1_PLL_BYP1_P029" (solid, remove dead copper, pour order 29): 162.3,132.938 162.3,132.299 164.439,132.299 164.439,132.938
PVDD_CONN on L1 "L1_PVDD_CONN_P159" (solid, remove dead copper, pour order 159): 132,139 137,139 138,138 138,130.5 132,130.5
PVDD on L1 "L1_PVDD_P091" (solid, remove dead copper, pour order 91): 159.6,157.36 159.6,143.16 156.25,143.16 156.25,157.36
OUT_4P_J1 on L1 "L1_OUT_4P_J1_P158" (solid, remove dead copper, pour order 158): 182.75,124 182.75,116.75 185.25,116.75 185.25,124
OUT_2P_J1 on L1 "L1_OUT_2P_J1_P155" (solid, remove dead copper, pour order 155): 153.25,116.75 153.25,124 150.75,124 150.75,116.75
OUT_3P_J1 on L1 "L1_OUT_3P_J1_P151" (solid, remove dead copper, pour order 151): 182.75,133.25 182.75,126 185.25,126 185.25,133.25
OUT_1P_J1 on L1 "L1_OUT_1P_J1_P142" (solid, remove dead copper, pour order 142): 153.25,126 153.25,133.25 150.75,133.25 150.75,126
OUT_4P1 on L1 "L1_OUT_4P1_P140" (solid, remove dead copper, pour order 140): 177.75,120.25 179.75,120.25 179.75,123.75 177.75,123.75
OUT_3P1 on L1 "L1_OUT_3P1_P134" (solid, remove dead copper, pour order 134): 177.75,126.25 179.75,126.25 179.75,129.75 177.75,129.75
OUT_1P1 on L1 "L1_OUT_1P1_P133" (solid, remove dead copper, pour order 133): 158.25,129.75 156.25,129.75 156.25,126.25 158.25,126.25
OUT_2P1 on L1 "L1_OUT_2P1_P132" (solid, remove dead copper, pour order 132): 158.25,123.75 156.25,123.75 156.25,120.25 158.25,120.25
OUT_4M_J1 on L1 "L1_OUT_4M_J1_P131" (solid, remove dead copper, pour order 131): 182.5,116.75 182.5,118.75 179,118.75 179,116.75
OUT_2M_J1 on L1 "L1_OUT_2M_J1_P106" (solid, remove dead copper, pour order 106): 153.5,118.75 153.5,116.75 157,116.75 157,118.75
OUT_3M_J1 on L1 "L1_OUT_3M_J1_P105" (solid, remove dead copper, pour order 105): 182.5,131.25 182.5,133.25 179,133.25 179,131.25
OUT_1M_J1 on L1 "L1_OUT_1M_J1_P104" (solid, remove dead copper, pour order 104): 153.5,133.25 153.5,131.25 157,131.25 157,133.25
OUT_3P1 on L1 "L1_OUT_3P1_P103" (solid, remove dead copper, pour order 103): 171.4,124.993 170.164,124.993 cw(c170.164,125.256) 169.9,125.256 169.9,126.156 cw(c170.136,126.156) 170.136,126.393 171.4,126.393 cw(c171.4,126.193) 171.6,126.193 171.6,125.193 cw(c171.4,125.193)
OUT_4P1 on L1 "L1_OUT_4P1_P101" (solid, remove dead copper, pour order 101): 171.4,123.653 170.164,123.653 cw(c170.164,123.917) 169.9,123.917 169.9,124.817 cw(c170.136,124.817) 170.136,125.053 171.4,125.053 cw(c171.4,124.853) 171.6,124.853 171.6,123.853 cw(c171.4,123.853)
OUT_1P1 on L1 "L1_OUT_1P1_P099" (solid, remove dead copper, pour order 99): 164.6,126.337 165.836,126.337 cw(c165.836,126.074) 166.1,126.074 166.1,125.174 cw(c165.864,125.174) 165.864,124.937 164.6,124.937 cw(c164.6,125.137) 164.4,125.137 164.4,126.137 cw(c164.6,126.137)
OUT_2P1 on L1 "L1_OUT_2P1_P097" (solid, remove dead copper, pour order 97): 164.6,125.064 165.836,125.064 cw(c165.836,124.8) 166.1,124.8 166.1,123.9 cw(c165.864,123.9) 165.864,123.664 164.6,123.664 cw(c164.6,123.864) 164.4,123.864 164.4,124.864 cw(c164.6,124.864)
OUT_2M_J1 on L1 "L1_OUT_2M_J1_P095" (solid, remove dead copper, pour order 95): 164.6,121.882 165.6,121.882 cw(c165.6,121.682) 165.8,121.682 165.8,120.682 cw(c165.6,120.682) 165.6,120.482 164.6,120.482 cw(c164.6,120.682) 164.4,120.682 164.4,121.682 cw(c164.6,121.682)
OUT_4M_J1 on L1 "L1_OUT_4M_J1_P094" (solid, remove dead copper, pour order 94): 170.42,122.527 171.42,122.527 cw(c171.42,122.327) 171.62,122.327 171.62,121.327 cw(c171.42,121.327) 171.42,121.127 170.42,121.127 cw(c170.42,121.327) 170.22,121.327 170.22,122.327 cw(c170.42,122.327)
OUT_3M_J1 on L1 "L1_OUT_3M_J1_P093" (solid, remove dead copper, pour order 93): 170.419,129.509 171.419,129.509 cw(c171.419,129.309) 171.619,129.309 171.619,128.309 cw(c171.419,128.309) 171.419,128.109 170.419,128.109 cw(c170.419,128.309) 170.219,128.309 170.219,129.309 cw(c170.419,129.309)
OUT_1M_J1 on L1 "L1_OUT_1M_J1_P092" (solid, remove dead copper, pour order 92): 164.6,129.5 165.6,129.5 cw(c165.6,129.3) 165.8,129.3 165.8,128.3 cw(c165.6,128.3) 165.6,128.1 164.6,128.1 cw(c164.6,128.3) 164.4,128.3 164.4,129.3 cw(c164.6,129.3)
OUT_4P0 on L1 "L1_OUT_4P0_P090" (solid, remove dead copper, pour order 90): 177.75,170.25 179.75,170.25 179.75,173.75 177.75,173.75
OUT_3P0 on L1 "L1_OUT_3P0_P089" (solid, remove dead copper, pour order 89): 177.75,176.25 179.75,176.25 179.75,179.75 177.75,179.75
OUT_1P0 on L1 "L1_OUT_1P0_P088" (solid, remove dead copper, pour order 88): 158.25,179.75 156.25,179.75 156.25,176.25 158.25,176.25
OUT_2P0 on L1 "L1_OUT_2P0_P087" (solid, remove dead copper, pour order 87): 158.25,173.75 156.25,173.75 156.25,170.25 158.25,170.25
OUT_4P_J0 on L1 "L1_OUT_4P_J0_P086" (solid, remove dead copper, pour order 86): 182.75,174 182.75,166.75 185.25,166.75 185.25,174
OUT_4M_J0 on L1 "L1_OUT_4M_J0_P064" (solid, remove dead copper, pour order 64): 182.5,166.75 182.5,168.75 179,168.75 179,166.75
OUT_2P_J0 on L1 "L1_OUT_2P_J0_P063" (solid, remove dead copper, pour order 63): 153.25,166.75 153.25,174 150.75,174 150.75,166.75
OUT_2M_J0 on L1 "L1_OUT_2M_J0_P062" (solid, remove dead copper, pour order 62): 153.5,168.75 153.5,166.75 157,166.75 157,168.75
OUT_3P_J0 on L1 "L1_OUT_3P_J0_P061" (solid, remove dead copper, pour order 61): 182.75,183.25 182.75,176 185.25,176 185.25,183.25
OUT_3M_J0 on L1 "L1_OUT_3M_J0_P060" (solid, remove dead copper, pour order 60): 182.5,181.25 182.5,183.25 179,183.25 179,181.25
OUT_1P_J0 on L1 "L1_OUT_1P_J0_P059" (solid, remove dead copper, pour order 59): 153.25,176 153.25,183.25 150.75,183.25 150.75,176
OUT_1M_J0 on L1 "L1_OUT_1M_J0_P058" (solid, remove dead copper, pour order 58): 153.5,183.25 153.5,181.25 157,181.25 157,183.25
OUT_3P0 on L1 "L1_OUT_3P0_P057" (solid, remove dead copper, pour order 57): 171.4,174.993 170.164,174.993 cw(c170.164,175.256) 169.9,175.256 169.9,176.156 cw(c170.136,176.156) 170.136,176.393 171.4,176.393 cw(c171.4,176.193) 171.6,176.193 171.6,175.193 cw(c171.4,175.193)
OUT_4P0 on L1 "L1_OUT_4P0_P055" (solid, remove dead copper, pour order 55): 171.4,173.653 170.164,173.653 cw(c170.164,173.917) 169.9,173.917 169.9,174.817 cw(c170.136,174.817) 170.136,175.053 171.4,175.053 cw(c171.4,174.853) 171.6,174.853 171.6,173.853 cw(c171.4,173.853)
OUT_1P0 on L1 "L1_OUT_1P0_P054" (solid, remove dead copper, pour order 54): 164.6,176.337 165.836,176.337 cw(c165.836,176.074) 166.1,176.074 166.1,175.174 cw(c165.864,175.174) 165.864,174.937 164.6,174.937 cw(c164.6,175.137) 164.4,175.137 164.4,176.137 cw(c164.6,176.137)
OUT_2P0 on L1 "L1_OUT_2P0_P053" (solid, remove dead copper, pour order 53): 164.6,175.064 165.836,175.064 cw(c165.836,174.8) 166.1,174.8 166.1,173.9 cw(c165.864,173.9) 165.864,173.664 164.6,173.664 cw(c164.6,173.864) 164.4,173.864 164.4,174.864 cw(c164.6,174.864)
OUT_2M_J0 on L1 "L1_OUT_2M_J0_P052" (solid, remove dead copper, pour order 52): 164.6,171.882 165.6,171.882 cw(c165.6,171.682) 165.8,171.682 165.8,170.682 cw(c165.6,170.682) 165.6,170.482 164.6,170.482 cw(c164.6,170.682) 164.4,170.682 164.4,171.682 cw(c164.6,171.682)
OUT_4M_J0 on L1 "L1_OUT_4M_J0_P049" (solid, remove dead copper, pour order 49): 170.42,172.527 171.42,172.527 cw(c171.42,172.327) 171.62,172.327 171.62,171.327 cw(c171.42,171.327) 171.42,171.127 170.42,171.127 cw(c170.42,171.327) 170.22,171.327 170.22,172.327 cw(c170.42,172.327)
OUT_3M_J0 on L1 "L1_OUT_3M_J0_P048" (solid, remove dead copper, pour order 48): 170.419,179.509 171.419,179.509 cw(c171.419,179.309) 171.619,179.309 171.619,178.309 cw(c171.419,178.309) 171.419,178.109 170.419,178.109 cw(c170.419,178.309) 170.219,178.309 170.219,179.309 cw(c170.419,179.309)
OUT_1M_J0 on L1 "L1_OUT_1M_J0_P047" (solid, remove dead copper, pour order 47): 164.6,179.5 165.6,179.5 cw(c165.6,179.3) 165.8,179.3 165.8,178.3 cw(c165.6,178.3) 165.6,178.1 164.6,178.1 cw(c164.6,178.3) 164.4,178.3 164.4,179.3 cw(c164.6,179.3)
PVDD on L1 "L1_PVDD_P046" (solid, remove dead copper, pour order 46): 148,148.66 151,148.66 151,143.16 148,143.16
PVDD on L1 "L1_PVDD_P045" (solid, remove dead copper, pour order 45): 148,157.36 151,157.36 151,151.86 148,151.86
GND on L1 "L1_GND_P030" (solid, remove dead copper, pour order 30): 148,165.4 151,165.4 151,159.865 148,159.865
GND on L1 "L1_GND_P031" (solid, remove dead copper, pour order 31): 148,140.8 151,140.8 151,135.3 148,135.3
VIN1_SRC on L1 "L1_VIN1_SRC_P043" (solid, remove dead copper, pour order 43): 137,139.247 133,139.247 133,141.5 133,143.395 137,143.395
OUT_3P_J0 on L3 "L3_OUT_3P_J0_P083" (solid, remove dead copper, pour order 83): 182.75,180.5 182.75,183.125 187,183.125 187,180.5
OUT_3P_J0 on L3 "L3_OUT_3P_J0_P071" (solid, remove dead copper, pour order 71): 206,185.5 206,180.5 185.5,180.5 185.5,183 188,185.5
OUT_1P_J0 on L3 "L3_OUT_1P_J0_P117" (solid, remove dead copper, pour order 117): 170,188.25 180,198.25 194.31,198.25 194.31,190.25 184.5,190.25 180.25,186 170,186
OUT_1P_J0 on L3 "L3_OUT_1P_J0_P021" (solid, remove dead copper, pour order 21): 150.75,180.5 154.5,180.5 154.5,184.5 156,186 170.5,186 170.5,188.25 153.26,188.25 150.75,185.74
OUT_1M_J0 on L3 "L3_OUT_1M_J0_P076" (solid, remove dead copper, pour order 76): 166,178 166,179.75 164,181.75 156.75,181.75 156.75,183.5 170.5,183.5 170.5,185.75 156,185.75 154.5,184.25 154.5,180.5 155.5,179.5 162,179.5 163.5,178
OUT_1M_J0 on L3 "L3_OUT_1M_J0_P112" (solid, remove dead copper, pour order 112): 170,185.75 180,185.75 184.5,190.25 194,190.25 198,194.25 207.75,194.25 210.75,197.25 216.375,191.625 211.75,187 187.25,187 183.75,183.5 170,183.5
OUT_2M_J0 on L3 "L3_OUT_2M_J0_P077" (solid, remove dead copper, pour order 77): 166,171.976 166,170.254 163.746,168 156.75,168 156.75,166.463 170.5,166.463 170.5,164.226 156,164.226 154.5,165.726 154.5,168.726 156.024,170.25 162.024,170.25 163.75,171.976
OUT_2M_J0 on L3 "L3_OUT_2M_J0_P116" (solid, remove dead copper, pour order 116): 170,166.447 170,164.226 178.774,164.226 182.75,160.25 202.5,160.25 206.5,156.25 217.5,156.25 220.25,153.25 225.875,158.875 221,163.75 185.5,163.75 182.803,166.447 179.5,166.447
OUT_2P_J0 on L3 "L3_OUT_2P_J0_P008" (solid, remove dead copper, pour order 8): 150.546,169.494 154.296,169.494 154.296,165.744 155.786,164.253 170.296,164.253 170.296,161.75 153.049,161.75 150.546,164.253
OUT_2P_J0 on L3 "L3_OUT_2P_J0_P111" (solid, remove dead copper, pour order 111): 170,161.75 179.54,152.21 203.835,152.21 203.835,160.21 182.79,160.21 178.963,164.037 170,164.037
OUT_3M_J0 on L3 "L3_OUT_3M_J0_P073" (solid, remove dead copper, pour order 73): 170,177.75 173,177.75 175,179.75 178.5,179.75 182.25,176 186.25,176 186.25,180.25 183.75,180.25 180.75,183.25 175,183.25 171.5,179.75 170,179.75
OUT_3M_J0 on L3 "L3_OUT_3M_J0_P115" (solid, remove dead copper, pour order 115): 185.5,176 221,176 226,181 220.25,186.75 217,183.5 207.405,183.5 204.155,180.25 185.5,180.25
OUT_4M_J0 on L3 "L3_OUT_4M_J0_P072" (solid, remove dead copper, pour order 72): 170,172.75 173,172.75 175.25,170.5 178.75,170.5 182.75,174.5 186.25,174.5 186.25,170 183.75,170 180.75,167 175.25,167 171.5,170.75 170,170.75
OUT_4M_J0 on L3 "L3_OUT_4M_J0_P114" (solid, remove dead copper, pour order 114): 185.5,174.5 211.5,174.5 216.5,169.5 210.75,163.75 207.533,167 196.75,167 193.75,170 185.5,170
OUT_4P_J0 on L3 "L3_OUT_4P_J0_P084" (solid, remove dead copper, pour order 84): 182.75,167 182.75,169.75 187,169.75 187,167
OUT_4P_J0 on L3 "L3_OUT_4P_J0_P113" (solid, remove dead copper, pour order 113): 194.5,164.5 194.5,169.75 185.75,169.75 185.75,167 188.25,164.5
VSYS5V0 on L3 "L3_VSYS5V0_P001" (solid, remove dead copper, pour order 1): 109,128.102 109,170.358 113,170.358 113,166.796 110.864,166.796 110.864,155.636 113,153.5 113,133 119.359,133 119.359,120.5 119.359,102 106,102 106,125.102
